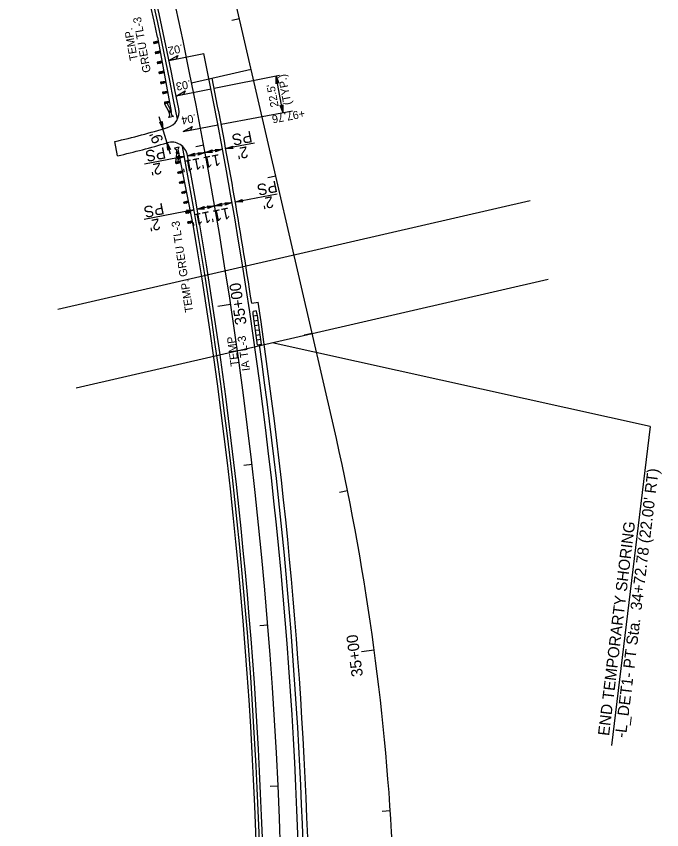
# Model space of a CAD drawing. Extents: x 473658 to 481584, y 489119 to 506230.
# Drawn here: x 481178 to 481578, y 491468 to 491971 of the extents above; entities that cross this region are included whole.
import ezdxf

# ---------------------------------------------------------------- set-up
doc = ezdxf.new("R2010")
doc.units = 0
for name, color, linetype in [('Exist Horizontal Alignment', 7, 'Continuous'), ('Exist Structure Minor Culvert Topo', 7, 'Continuous'), ('Exist Structure Minor Pipes RCP 12 Inch Leader', 7, 'Continuous'), ('Prop Conc Barrier', 7, 'Continuous'), ('Prop Dimension', 7, 'Continuous'), ('Prop EOT', 7, 'Continuous'), ('Prop Guardrail', 7, 'Continuous'), ('Prop Guardrail Anchor Unit CELL', 7, 'Continuous'), ('Prop Horizontal Alignment', 7, 'Continuous'), ('Prop Horizontal Alignment Tick Label', 7, 'Continuous'), ('Prop Horizontal Alignment Tick Large', 7, 'Continuous'), ('Prop Horizontal Alignment Tick Small', 7, 'Continuous'), ('Prop Paved Shoulder', 7, 'Continuous'), ('Prop Superelevation  Arrow CELL', 7, 'Continuous'), ('Prop Superelevation Label', 7, 'Continuous'), ('Scratch_Level_0', 7, 'Continuous'), ('Scratch_Level_6', 7, 'Continuous'), ('Sheet Plan And Profile CELL', 7, 'Continuous'), ('Sheet Profile Grid Major CELL', 7, 'Continuous')]:
    doc.layers.add(name, color=color, linetype=linetype)

msp = doc.modelspace()

# ---------------------------------------------------------------- linework, layer by layer
at = {"layer": 'Exist Horizontal Alignment'}
for points in [[(481268.84, 491906.15), (481269.23, 491901.6), (481267.31, 491905.77), (481268.23, 491905.42)], [(481272.37, 491888.44), (481271.82, 491892.98), (481273.89, 491888.87), (481272.95, 491889.19)], [(481301.63, 491888.92), (481306.2, 491889), (481301.9, 491887.37), (481302.32, 491888.26)], [(481312.73, 491889.46), (481308.16, 491889.38), (481312.46, 491891.01), (481312.04, 491890.12)], [(481278.06, 491884.43), (481282.62, 491884.51), (481278.33, 491882.88), (481278.74, 491883.77)], [(481289.15, 491884.97), (481284.59, 491884.89), (481288.88, 491886.52), (481288.47, 491885.63)], [(481290.83, 491886.86), (481295.39, 491886.95), (481291.1, 491885.31), (481291.51, 491886.21)], [(481299.96, 491887.03), (481295.39, 491886.95), (481299.69, 491888.58), (481299.27, 491887.68)], [(481296.75, 491853.81), (481301.31, 491853.89), (481297.02, 491852.26), (481297.43, 491853.15)], [(481305.88, 491853.97), (481301.31, 491853.89), (481305.61, 491855.52), (481305.19, 491854.63)], [(481307.55, 491855.87), (481312.12, 491855.95), (481307.82, 491854.31), (481308.24, 491855.21)], [(481318.65, 491856.4), (481314.08, 491856.32), (481318.38, 491857.95), (481317.96, 491857.06)], [(481283.97, 491851.37), (481288.54, 491851.46), (481284.24, 491849.82), (481284.66, 491850.72)], [(481295.07, 491851.91), (481290.5, 491851.83), (481294.8, 491853.46), (481294.39, 491852.57)]]:
    msp.add_lwpolyline(points, close=True, dxfattribs=at)
at = {"layer": 'Exist Structure Minor Pipes RCP 12 Inch Leader'}
for p, q in [((481326.08, 491788.74), (481325.09, 491788.6)), ((481325.12, 491786.59), (481325.09, 491788.6)), ((481327.07, 491788.88), (481326.08, 491788.74)), ((481327.6, 491786.94), (481327.07, 491788.88)), ((481325.26, 491785.6), (481325.12, 491786.59)), ((481327.74, 491785.95), (481325.26, 491785.6)), ((481325.68, 491782.63), (481325.26, 491785.6)), ((481327.74, 491785.95), (481327.6, 491786.94)), ((481328.16, 491782.98), (481327.74, 491785.95)), ((481328.16, 491782.98), (481325.68, 491782.63)), ((481326.1, 491779.66), (481325.68, 491782.63)), ((481328.58, 491780), (481326.1, 491779.66)), ((481326.52, 491776.69), (481326.1, 491779.66)), ((481328.58, 491780), (481328.16, 491782.98)), ((481328.99, 491777.03), (481328.58, 491780)), ((481328.99, 491777.03), (481326.52, 491776.69)), ((481326.94, 491773.71), (481326.52, 491776.69)), ((481329.41, 491774.06), (481326.94, 491773.71)), ((481327.35, 491770.74), (481326.94, 491773.71)), ((481329.41, 491774.06), (481328.99, 491777.03)), ((481329.83, 491771.09), (481329.41, 491774.06)), ((481329.83, 491771.09), (481327.35, 491770.74)), ((481327.77, 491767.77), (481327.35, 491770.74)), ((481330.25, 491768.12), (481327.77, 491767.77)), ((481330.25, 491768.12), (481329.83, 491771.09))]:
    msp.add_line(p, q, dxfattribs=at)
at = {"layer": 'Prop Conc Barrier'}
msp.add_arc((478448.2, 491360.34), 2909.5, 353.03651, 8.05328, dxfattribs=at)
at = {"layer": 'Prop Dimension'}
for p, q in [((481273.89, 491886.06), (481267.01, 491909)), ((481306.2, 491889), (481284.59, 491884.89)), ((481326.02, 491892.78), (481308.16, 491889.38)), ((481282.62, 491884.51), (481257.9, 491879.8)), ((481339.94, 491861.25), (481314.08, 491856.32)), ((481312.12, 491855.95), (481290.5, 491851.83)), ((481288.54, 491851.46), (481257.6, 491845.56))]:
    msp.add_line(p, q, dxfattribs=at)
at = {"layer": 'Prop EOT'}
msp.add_line((481241.24, 491884.96), (481239.56, 491893.8), dxfattribs=at)
for centre, radius, start, end in [((478448.7, 491360.28), 2884, 11.06869, 18.70399), ((478448.7, 491360.28), 2906, 353.03651, 11.67572), ((481269.24, 491912.05), 10, 287.0871, 11.0687), ((481141.28, 492328.33), 445.5, 282.7454, 287.0871), ((481141.28, 492328.33), 454.5, 282.7055, 286.6917), ((481274.69, 491883.4), 10, 10.4872, 106.6917), ((478448.7, 491360.28), 2884, 353.03651, 10.48724)]:
    msp.add_arc(centre, radius, start, end, dxfattribs=at)
at = {"layer": 'Prop Guardrail'}
for start, end in [(11.98546, 18.45113), (359.16561, 9.61015)]:
    msp.add_arc((478448.7, 491360.28), 2880, start, end, dxfattribs=at)
at = {"layer": 'Prop Guardrail Anchor Unit CELL'}
for p, q in [((481266.37, 491955.85), (481263.42, 491955.31)), ((481265.08, 491954.6), (481263.42, 491955.31)), ((481263.42, 491955.31), (481263.6, 491954.33)), ((481263.6, 491954.33), (481264.9, 491955.58)), ((481266.55, 491954.87), (481263.6, 491954.33)), ((481264.9, 491955.58), (481265.08, 491954.6)), ((481264.9, 491955.58), (481266.55, 491954.87)), ((481265.08, 491954.6), (481266.37, 491955.85)), ((481266.55, 491954.87), (481265.08, 491954.6)), ((481265.92, 491958.35), (481274.33, 491912.37)), ((481266.37, 491955.85), (481266.55, 491954.87)), ((481267.51, 491949.66), (481264.51, 491949.11)), ((481267.51, 491949.66), (481266.19, 491948.4)), ((481266.19, 491948.4), (481264.51, 491949.11)), ((481264.51, 491949.11), (481264.69, 491948.12)), ((481264.69, 491948.12), (481266.01, 491949.38)), ((481267.69, 491948.67), (481264.69, 491948.12)), ((481266.01, 491949.38), (481266.19, 491948.4)), ((481266.01, 491949.38), (481267.69, 491948.67)), ((481268.64, 491943.46), (481265.65, 491942.91)), ((481267.32, 491942.2), (481265.65, 491942.91)), ((481265.65, 491942.91), (481265.83, 491941.92)), ((481265.83, 491941.92), (481267.14, 491943.18)), ((481268.82, 491942.47), (481265.83, 491941.92)), ((481267.14, 491943.18), (481267.32, 491942.2)), ((481267.14, 491943.18), (481268.82, 491942.47)), ((481268.64, 491943.46), (481267.32, 491942.2)), ((481269.78, 491937.26), (481266.79, 491936.71)), ((481268.46, 491936), (481266.79, 491936.71)), ((481266.79, 491936.71), (481266.97, 491935.73)), ((481266.97, 491935.73), (481268.28, 491936.98)), ((481269.96, 491936.27), (481266.97, 491935.73)), ((481268.28, 491936.98), (481268.46, 491936)), ((481268.28, 491936.98), (481269.96, 491936.27)), ((481269.78, 491937.26), (481268.46, 491936)), ((481269.78, 491937.26), (481269.96, 491936.27)), ((481270.91, 491931.06), (481267.83, 491930.5)), ((481269.55, 491929.79), (481267.83, 491930.5)), ((481267.83, 491930.5), (481268.01, 491929.51)), ((481268.01, 491929.51), (481269.37, 491930.78)), ((481271.09, 491930.08), (481268.01, 491929.51)), ((481269.37, 491930.78), (481269.55, 491929.79)), ((481269.37, 491930.78), (481271.09, 491930.08)), ((481270.91, 491931.06), (481269.55, 491929.79)), ((481272.05, 491924.86), (481269.1, 491924.32)), ((481270.75, 491923.61), (481269.1, 491924.32)), ((481269.1, 491924.32), (481269.28, 491923.34)), ((481269.28, 491923.34), (481270.57, 491924.59)), ((481270.57, 491924.59), (481270.75, 491923.61)), ((481270.57, 491924.59), (481272.23, 491923.88)), ((481272.05, 491924.86), (481270.75, 491923.61)), ((481272.23, 491923.88), (481269.28, 491923.34)), ((481273.18, 491918.66), (481270.17, 491918.11)), ((481271.85, 491917.4), (481270.17, 491918.11)), ((481270.17, 491918.11), (481270.35, 491917.13)), ((481270.35, 491917.13), (481271.67, 491918.39)), ((481273.36, 491917.68), (481270.35, 491917.13)), ((481270.35, 491917.13), (481272.77, 491912.59)), ((481271.67, 491918.39), (481271.85, 491917.4)), ((481271.67, 491918.39), (481273.36, 491917.68)), ((481273.18, 491918.66), (481271.85, 491917.4)), ((481271.85, 491917.4), (481274.24, 491912.86)), ((481274.24, 491912.86), (481272.77, 491912.59)), ((481272.77, 491912.59), (481272.86, 491912.1)), ((481274.42, 491911.87), (481272.77, 491912.59)), ((481272.77, 491912.59), (481272.95, 491911.6)), ((481272.86, 491908.75), (481273.47, 491910.07)), ((481275.75, 491909.33), (481272.86, 491908.75)), ((481272.95, 491911.6), (481274.24, 491912.86)), ((481274.42, 491911.87), (481272.95, 491911.6)), ((481273.07, 491912.08), (481273.67, 491912.2)), ((481273.47, 491910.07), (481273.07, 491912.08)), ((481273.67, 491912.2), (481274.26, 491912.32)), ((481274.26, 491912.32), (481274.67, 491910.31)), ((481274.67, 491910.31), (481275.75, 491909.33)), ((481279.38, 491890.28), (481276.49, 491889.76)), ((481276.49, 491889.76), (481277.54, 491888.75)), ((481278.74, 491888.97), (481279.38, 491890.28)), ((481277.23, 491881.04), (481277.81, 491886.16)), ((481277.54, 491888.75), (481277.9, 491886.74)), ((481279.09, 491887.43), (481277.62, 491887.14)), ((481277.81, 491886.16), (481277.62, 491887.14)), ((481277.62, 491887.14), (481279.28, 491886.45)), ((481277.81, 491886.16), (481277.72, 491886.65)), ((481279.09, 491887.43), (481277.81, 491886.16)), ((481279.28, 491886.45), (481277.81, 491886.16)), ((481277.9, 491886.74), (481278.51, 491886.85)), ((481278.51, 491886.85), (481279.11, 491886.96)), ((481278.73, 491881.34), (481279.28, 491886.45)), ((481279.11, 491886.96), (481278.74, 491888.97)), ((481288.28, 491841.08), (481279.19, 491886.94)), ((481280.24, 491881.64), (481277.23, 491881.04)), ((481277.43, 491880.06), (481277.23, 491881.04)), ((481277.23, 491881.04), (481278.93, 491880.36)), ((481278.73, 491881.34), (481277.43, 491880.06)), ((481280.43, 491880.66), (481277.43, 491880.06)), ((481278.93, 491880.36), (481278.73, 491881.34)), ((481280.43, 491880.66), (481278.73, 491881.34)), ((481278.93, 491880.36), (481280.24, 491881.64)), ((481281.46, 491875.46), (481278.52, 491874.88)), ((481278.72, 491873.89), (481278.52, 491874.88)), ((481278.52, 491874.88), (481280.19, 491874.19)), ((481279.99, 491875.17), (481278.72, 491873.89)), ((481281.66, 491874.48), (481278.72, 491873.89)), ((481280.19, 491874.19), (481279.99, 491875.17)), ((481281.66, 491874.48), (481279.99, 491875.17)), ((481280.19, 491874.19), (481281.46, 491875.46)), ((481282.69, 491869.28), (481279.61, 491868.67)), ((481281.15, 491868.97), (481279.81, 491867.69)), ((481281.35, 491867.99), (481281.15, 491868.97)), ((481282.88, 491868.3), (481281.15, 491868.97)), ((481281.35, 491867.99), (481282.69, 491869.28)), ((481279.81, 491867.69), (481279.61, 491868.67)), ((481279.61, 491868.67), (481281.35, 491867.99)), ((481282.88, 491868.3), (481279.81, 491867.69)), ((481283.92, 491863.1), (481280.94, 491862.51)), ((481281.13, 491861.53), (481280.94, 491862.51)), ((481280.94, 491862.51), (481282.62, 491861.82)), ((481282.43, 491862.8), (481281.13, 491861.53)), ((481284.11, 491862.12), (481281.13, 491861.53)), ((481282.62, 491861.82), (481282.43, 491862.8)), ((481284.11, 491862.12), (481282.43, 491862.8)), ((481282.62, 491861.82), (481283.92, 491863.1)), ((481284.11, 491862.12), (481283.92, 491863.1)), ((481285.14, 491856.92), (481282.15, 491856.32)), ((481282.35, 491855.34), (481282.15, 491856.32)), ((481282.15, 491856.32), (481283.84, 491855.64)), ((481283.65, 491856.62), (481282.35, 491855.34)), ((481285.34, 491855.94), (481282.35, 491855.34)), ((481283.84, 491855.64), (481283.65, 491856.62)), ((481285.34, 491855.94), (481283.65, 491856.62)), ((481283.84, 491855.64), (481285.14, 491856.92)), ((481286.37, 491850.74), (481283.37, 491850.14)), ((481283.57, 491849.16), (481283.37, 491850.14)), ((481283.37, 491850.14), (481285.07, 491849.46)), ((481284.87, 491850.44), (481283.57, 491849.16)), ((481286.56, 491849.76), (481283.57, 491849.16)), ((481285.07, 491849.46), (481284.87, 491850.44)), ((481286.56, 491849.76), (481284.87, 491850.44)), ((481285.07, 491849.46), (481286.37, 491850.74)), ((481287.59, 491844.56), (481284.65, 491843.97)), ((481284.85, 491842.99), (481284.65, 491843.97)), ((481284.65, 491843.97), (481286.32, 491843.28)), ((481286.12, 491844.26), (481284.85, 491842.99)), ((481287.59, 491844.56), (481286.12, 491844.26)), ((481286.32, 491843.28), (481286.12, 491844.26)), ((481286.12, 491844.26), (481287.79, 491843.57)), ((481286.32, 491843.28), (481287.59, 491844.56)), ((481287.79, 491843.57), (481287.59, 491844.56)), ((481287.79, 491843.57), (481284.85, 491842.99))]:
    msp.add_line(p, q, dxfattribs=at)
at = {"layer": 'Prop Horizontal Alignment'}
msp.add_line((481374.81, 491717.83), (481188.8, 492524.78), dxfattribs=at)
for centre, radius, end in [((478448.7, 491360.28), 2895, 18.70399), ((479903.4, 491378.64), 1510, 12.98112)]:
    msp.add_arc(centre, radius, 353.03651, end, dxfattribs=at)
at = {"layer": 'Prop Horizontal Alignment Tick Large'}
for p, q in [((481311.19, 491792.92), (481303.28, 491791.72)), ((481400.08, 491578.77), (481392.15, 491577.71))]:
    msp.add_line(p, q, dxfattribs=at)
at = {"layer": 'Prop Horizontal Alignment Tick Small'}
for p, q in [((481316.72, 491969.83), (481311.85, 491968.71)), ((481294.54, 491891.52), (481289.63, 491890.6)), ((481339.19, 491872.39), (481334.31, 491871.26)), ((481361.65, 491774.94), (481356.78, 491773.82)), ((481324.43, 491693.8), (481319.46, 491693.22)), ((481383.56, 491677.38), (481378.66, 491676.39)), ((481334.23, 491594.28), (481329.24, 491593.87)), ((481340.59, 491494.48), (481335.59, 491494.25)), ((481410.05, 491479.29), (481405.06, 491478.95))]:
    msp.add_line(p, q, dxfattribs=at)
at = {"layer": 'Prop Paved Shoulder'}
msp.add_line((481324.22, 491793.69), (481328.18, 491794.24), dxfattribs=at)
for centre, radius, start, end in [((478448.7, 491360.28), 2882, 10.94924, 18.70399), ((478448.7, 491360.28), 2908, 8.57123, 11.36084), ((478448.7, 491360.28), 2882, 353.03651, 10.60669), ((478448.2, 491360.26), 2912.5, 353.03855, 8.56944)]:
    msp.add_arc(centre, radius, start, end, dxfattribs=at)
at = {"layer": 'Prop Superelevation  Arrow CELL'}
msp.add_line((481343.55, 491911.88), (481339.32, 491934.17), dxfattribs=at)
for points in [[(481273.03, 491943.92), (481278.5, 491947.1), (481277.56, 491944.86)], [(481339.39, 491929.6), (481339.32, 491934.17), (481340.95, 491929.87), (481340.05, 491930.29)], [(481277.48, 491921.95), (481282.97, 491925.08), (481282.01, 491922.85)], [(481343.47, 491916.45), (481343.55, 491911.88), (481341.92, 491916.18), (481342.81, 491915.76)], [(481281.76, 491899.95), (481287.28, 491903.04), (481286.3, 491900.81)]]:
    msp.add_lwpolyline(points, close=True, dxfattribs=at)
at = {"layer": 'Prop Superelevation Label'}
for p, q in [((481273.03, 491943.92), (481294.57, 491948.38)), ((481341.53, 491934.67), (481301.02, 491926.63)), ((481299.06, 491926.24), (481277.48, 491921.95)), ((481305.33, 491904.44), (481349.46, 491912.85)), ((481281.76, 491899.95), (481303.37, 491904.07))]:
    msp.add_line(p, q, dxfattribs=at)
at = {"layer": 'Scratch_Level_0'}
for q in [(481336.92, 491769.07), (481546.87, 491519.8)]:
    msp.add_line((481570.98, 491717.22), q, dxfattribs=at)
at = {"layer": 'Scratch_Level_6'}
msp.add_line((481287.05, 491930.2), (481323.9, 491938.7), dxfattribs=at)
at = {"layer": 'Sheet Plan And Profile CELL'}
for p, q in [((481204.25, 491789.97), (481496.58, 491857.36)), ((481215.48, 491741.25), (481507.82, 491808.64))]:
    msp.add_line(p, q, dxfattribs=at)

# ---------------------------------------------------------------- texts
at = {"layer": 'Exist Structure Minor Culvert Topo'}
for s, p in [('IA TL-3', (481323.25, 491752.03)), ('TEMP', (481316.25, 491754.93))]:
    msp.add_text(s, height=5, rotation=97.6024, dxfattribs=at).set_placement(p)
at = {"layer": 'Prop Guardrail Anchor Unit CELL'}
for s, rotation, p in [('GREU TL-3', 100.2943, (481261.83, 491936.9)), ('TEMP. ', 100.2943, (481253.81, 491944.4)), ('TEMP. GREU TL-3', 98.6724, (481288.04, 491788.36))]:
    msp.add_text(s, height=5, rotation=rotation, dxfattribs=at).set_placement(p)
at = {"layer": 'Prop Horizontal Alignment Tick Label'}
for rotation, p in [(98.5946, (481321.14, 491780.74)), (97.616, (481393.14, 491562.77))]:
    msp.add_text('35+00', height=7, rotation=rotation, dxfattribs=at).set_placement(p)
at = {"layer": 'Prop Superelevation  Arrow CELL'}
for s, rotation, p in [('(TYP.)', 100.7519, (481348.87, 491916.87)), ("22.5'", 100.7519, (481340.93, 491915.57)), ('+97.76', 190.7519, (481356.68, 491913.71))]:
    msp.add_text(s, height=5, rotation=rotation, dxfattribs=at).set_placement(p)
at = {"layer": 'Prop Superelevation Label'}
for s, rotation, p in [('.02', 191.6863, (481281.2, 491954.04)), ('.03', 191.2303, (481286.09, 491931.9)), ('.04', 190.785, (481289.48, 491910.84))]:
    msp.add_text(s, height=5, rotation=rotation, dxfattribs=at).set_placement(p)
at = {"layer": 'Scratch_Level_0'}
for s, p in [("-L_DET1- PT Sta.  34+72.78 (22.00' RT)", (481555.87, 491524.19)), ('END TEMPORARTY SHORING', (481545.45, 491525.46))]:
    msp.add_text(s, height=7, rotation=83.0365, dxfattribs=at).set_placement(p)
at = {"layer": 'Sheet Profile Grid Major CELL'}
for s, rotation, p in [('PS', 190.785, (481323.79, 491900.4)), ("9'", 112.2543, (481269.76, 491894.32)), ('PS', 190.785, (481270.23, 491890.33)), ("2'", 190.785, (481321.34, 491890.9)), ("11'", 190.785, (481304.19, 491886.05)), ("2'", 190.785, (481267.77, 491880.83)), ("11'", 190.785, (481292.27, 491883.78)), ('PS', 191.6803, (481339.29, 491869.56)), ("2'", 191.6803, (481336.98, 491860.03)), ('PS', 191.6803, (481269.17, 491855.84)), ("11'", 191.6803, (481298.13, 491850.77)), ("11'", 191.6803, (481310.04, 491853.04)), ("2'", 191.6803, (481266.87, 491846.3))]:
    msp.add_text(s, height=7, rotation=rotation, dxfattribs=at).set_placement(p)

doc.saveas('drawing.dxf')
